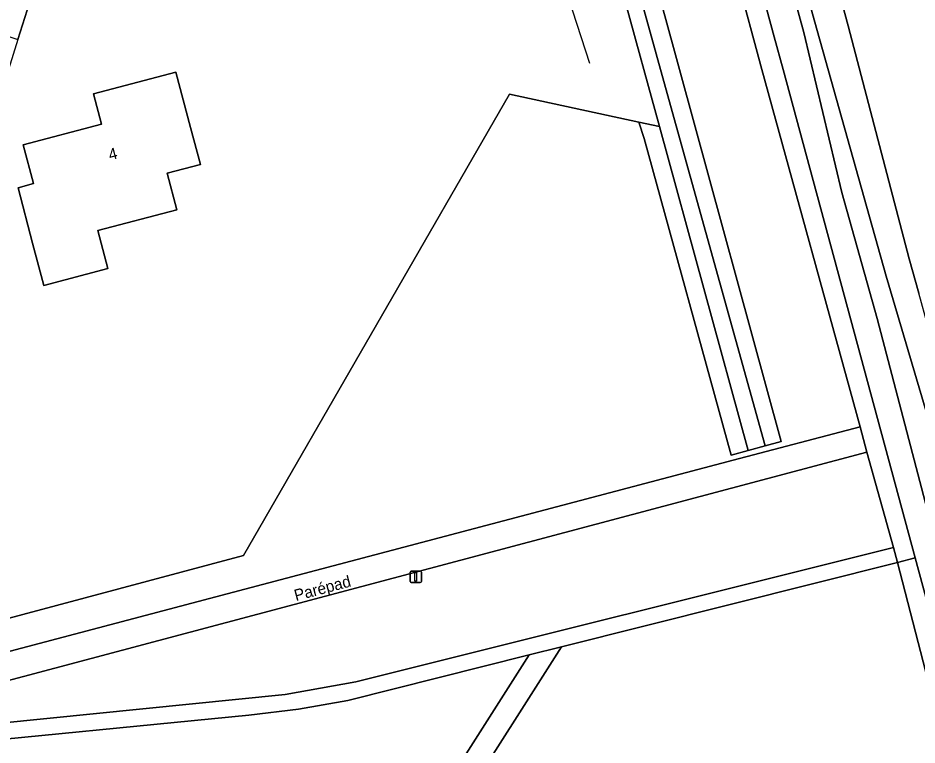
# Model space of a CAD drawing. Extents: x 162156 to 163172, y 378995 to 380779.
# Drawn here: x 162728.8 to 162807.3, y 380191 to 380254.5 of the extents above; entities that cross this region are included whole.
import ezdxf

# ---------------------------------------------------------------- set-up
doc = ezdxf.new("R2010")
doc.units = 0
for name, color, linetype in [('IMGEO_Erf', 7, 'Continuous'), ('IMGEO_Fietspad_gesloten', 7, 'Continuous'), ('IMGEO_Gemengd_bos', 7, 'Continuous'), ('IMGEO_Groenvoorziening', 7, 'Continuous'), ('IMGEO_Hek', 7, 'Continuous'), ('IMGEO_Lichtmast', 7, 'Continuous'), ('IMGEO_Naaldbos', 7, 'Continuous'), ('IMGEO_Openbare_ruimte_label', 7, 'Continuous'), ('IMGEO_Pand', 7, 'Continuous'), ('IMGEO_Pand_nummerreeks', 7, 'Continuous'), ('IMGEO_Rijbaan_lokaal_gesloten', 7, 'Continuous'), ('IMGEO_Rijbaan_lokaal_onverhard', 7, 'Continuous'), ('IMGEO_Voetpad_halfverhard', 7, 'Continuous'), ('IMGEO_Voetpad_open', 7, 'Continuous')]:
    doc.layers.add(name, color=color, linetype=linetype)

msp = doc.modelspace()

# ---------------------------------------------------------------- linework, layer by layer
at = {"layer": 'IMGEO_Erf'}
msp.add_lwpolyline([(162729.987, 380256.471), (162728.785, 380252.601), (162727.974, 380249.988), (162726.374, 380245.66), (162723.48, 380239.34), (162721.842, 380236.275), (162720.429, 380233.968), (162720.027, 380233.312), (162716.656, 380228.741), (162716.33, 380228.299), (162716.04, 380227.906), (162711.278, 380222.808), (162706.233, 380218.452), (162718.287, 380199.505), (162748.489, 380207.589), (162771.731, 380247.855), (162782.999, 380245.41), (162784.806, 380245.018), (162783.44, 380250), (162783.125, 380251.148), (162766.255, 380312.701)], dxfattribs=at)
msp.add_lwpolyline([(162743.866, 380244.932), (162744.719, 380241.706), (162741.817, 380240.939), (162742.658, 380237.76), (162735.759, 380235.935), (162736.634, 380232.624), (162731.048, 380231.146), (162730.07, 380234.846), (162728.792, 380239.679), (162730.144, 380240.037), (162729.246, 380243.433), (162736.069, 380245.237), (162735.376, 380247.858), (162742.588, 380249.765)], close=True, dxfattribs=at)
at = {"layer": 'IMGEO_Fietspad_gesloten'}
msp.add_lwpolyline([(162734.133, 380481.792), (162732.921, 380486.487), (162731.275, 380485.433), (162731.822, 380483.297), (162732.486, 380480.708), (162737.147, 380462.444), (162744.041, 380435.433), (162753.469, 380399.171), (162793.043, 380252.594), (162793.743, 380250), (162802.348, 380218.82), (162802.932, 380216.599), (162805.251, 380208.274), (162805.604, 380206.953), (162807.15, 380207.372), (162795.604, 380250), (162794.831, 380252.855), (162755.082, 380399.61), (162738.941, 380462.93)], close=True, dxfattribs=at)
at = {"layer": 'IMGEO_Gemengd_bos'}
for points in [[(162725.222, 380467.154), (162726.017, 380463.29), (162732.512, 380440.284), (162732.513, 380440.281), (162737.886, 380421.251), (162740.789, 380409.911), (162740.791, 380409.902), (162744.134, 380396.843), (162784.538, 380251.354), (162784.914, 380250), (162794.037, 380217.15), (162795.456, 380217.538), (162786.56, 380250), (162786.126, 380251.585), (162745.395, 380400.219)], [(162727.791, 380464.262), (162728.963, 380460.227), (162739.025, 380425.583), (162745.395, 380400.219), (162786.126, 380251.585), (162786.56, 380250), (162795.456, 380217.538), (162794.037, 380217.15), (162792.555, 380216.745), (162791.089, 380216.345), (162783.48, 380243.983), (162782.999, 380245.41), (162771.731, 380247.855), (162748.489, 380207.589), (162718.287, 380199.505), (162706.233, 380218.452), (162704.484, 380215.83), (162716.066, 380197.828)], [(162718.821, 380196.787), (162791.243, 380215.891), (162802.348, 380218.82), (162793.743, 380250), (162793.043, 380252.594), (162753.469, 380399.171)]]:
    msp.add_lwpolyline(points, dxfattribs=at)
for points in [[(162744.134, 380396.843), (162740.791, 380409.902), (162740.789, 380409.911), (162737.886, 380421.251), (162732.513, 380440.281), (162732.512, 380440.284), (162731.457, 380440.006), (162737.08, 380420.274), (162739.846, 380409.655), (162742.744, 380398.533), (162743.009, 380397.514), (162766.255, 380312.701), (162783.125, 380251.148), (162783.44, 380250), (162784.806, 380245.018), (162792.555, 380216.745), (162794.037, 380217.15), (162784.914, 380250), (162784.538, 380251.354)], [(162784.806, 380245.018), (162782.999, 380245.41), (162783.48, 380243.983), (162791.089, 380216.345), (162792.555, 380216.745)]]:
    msp.add_lwpolyline(points, close=True, dxfattribs=at)
at = {"layer": 'IMGEO_Groenvoorziening'}
for points in [[(162797.432, 380253.232), (162791.916, 380273.301), (162786.532, 380293.517), (162775.358, 380333.719), (162765.415, 380371.737), (162759.745, 380391.983), (162736.16, 380483.349), (162735.346, 380483.727), (162734.512, 380483.576)], [(162734.133, 380481.792), (162738.941, 380462.93), (162755.082, 380399.61), (162794.831, 380252.855), (162795.604, 380250), (162807.15, 380207.372), (162834.019, 380108.166), (162847.388, 380056.989), (162849.58, 380050.068), (162853.046, 380036.529), (162855.696, 380027.529), (162859.063, 380014.988), (162859.82, 380012.908), (162860.297, 380010.248), (162863.326, 380000), (162875.925, 379953.557)], [(162766.299, 380383.503), (162801.292, 380253.797), (162806.635, 380233.468), (162807.467, 380230.468)], [(162812.966, 380210.526), (162807.467, 380230.468), (162806.635, 380233.468), (162801.292, 380253.797), (162766.299, 380383.503)], [(162771.243, 380358.925), (162778.519, 380332.031), (162782.456, 380315.752), (162787.624, 380297.403), (162792.424, 380276.743), (162796.525, 380260.819), (162798.599, 380253.404), (162804.6, 380231.946), (162813.274, 380202.726), (162817.832, 380185.507), (162820.474, 380174.332), (162830.289, 380136.987), (162838.721, 380106.165), (162845.723, 380082.59), (162848.029, 380072.7), (162850.821, 380063.544), (162873.068, 379986.284), (162876.406, 379973.928), (162879.54, 379963.774)], [(162877.807, 379945.478), (162877.926, 379942.988), (162877.836, 379940.496), (162876.059, 379929.997), (162869.525, 379903.661), (162857.788, 379858.933), (162852.224, 379836.568), (162855.953, 379839.98), (162859.941, 379851.001), (162864.319, 379866.718), (162869.74, 379887.62), (162878.52, 379925.926), (162880.462, 379936.118), (162880.894, 379940.356), (162878.531, 379959.461), (162877.403, 379963.088), (162875.477, 379970.319), (162872.222, 379980.619), (162850.444, 380055.192), (162836.518, 380107.168), (162815.649, 380183.144), (162803.814, 380228.274), (162800.754, 380239.27), (162797.432, 380253.232)]]:
    msp.add_lwpolyline(points, dxfattribs=at)
at = {"layer": 'IMGEO_Hek'}
msp.add_lwpolyline([(162778.738, 380250.508), (162768.177, 380283.038), (162722.067, 380458.358), (162720.737, 380463.414)], dxfattribs=at)
at = {"layer": 'IMGEO_Lichtmast'}
for p, q in [((162763.028, 380205.309), (162763.028, 380206.109)), ((162763.028, 380206.109), (162763.028, 380205.309)), ((162763.128, 380206.209), (162763.918, 380206.209)), ((162763.918, 380206.209), (162763.128, 380206.209)), ((162764.018, 380206.109), (162764.018, 380205.309)), ((162764.018, 380205.309), (162764.018, 380206.109)), ((162763.918, 380205.209), (162763.128, 380205.209)), ((162763.128, 380205.209), (162763.918, 380205.209))]:
    msp.add_line(p, q, dxfattribs=at)
msp.add_lwpolyline([(162763.448, 380206.084), (162763.598, 380206.084), (162763.598, 380205.334), (162763.448, 380205.334), (162763.448, 380206.084)], dxfattribs=at)
for centre, start, end in [((162763.128, 380206.109), 90, 180), ((162763.128, 380206.109), 90, 180), ((162763.918, 380206.109), 0, 90), ((162763.918, 380206.109), 360, 90), ((162763.128, 380205.309), 180, 270), ((162763.128, 380205.309), 180, 270), ((162763.918, 380205.309), 270, 0), ((162763.918, 380205.309), 270, 0)]:
    msp.add_arc(centre, 0.1, start, end, dxfattribs=at)
at = {"layer": 'IMGEO_Naaldbos'}
for points in [[(162718.858, 380192.089), (162752.138, 380195.441), (162758.283, 380196.548), (162805.251, 380208.274), (162802.932, 380216.599), (162717.424, 380193.879)], [(162838.54, 380083.951), (162836.289, 380091.771), (162832.661, 380106.401), (162811.234, 380185.217), (162805.604, 380206.953), (162776.255, 380199.6), (162758.215, 380171.258), (162779.588, 380093.439), (162780.643, 380093.581), (162806.22, 380000)]]:
    msp.add_lwpolyline(points, dxfattribs=at)
msp.add_lwpolyline([(162721.056, 380190.903), (162731.803, 380187.774), (162737.024, 380185.747), (162742.813, 380182.703), (162750.127, 380178.223), (162753.063, 380176.112), (162756.789, 380172.742), (162773.434, 380198.894), (162757.585, 380194.923), (162753.291, 380194.171), (162748.964, 380193.637)], close=True, dxfattribs=at)
at = {"layer": 'IMGEO_Pand'}
msp.add_lwpolyline([(162743.866, 380244.932), (162742.588, 380249.765), (162735.376, 380247.858), (162736.069, 380245.237), (162729.246, 380243.433), (162730.144, 380240.037), (162728.792, 380239.679), (162730.07, 380234.846), (162731.048, 380231.146), (162736.634, 380232.624), (162735.759, 380235.935), (162742.658, 380237.76), (162741.817, 380240.939), (162744.719, 380241.706)], close=True, dxfattribs=at)
at = {"layer": 'IMGEO_Rijbaan_lokaal_gesloten'}
msp.add_lwpolyline([(162847.388, 380056.989), (162834.019, 380108.166), (162807.15, 380207.372), (162805.604, 380206.953), (162811.234, 380185.217), (162832.661, 380106.401), (162836.289, 380091.771), (162838.54, 380083.951)], dxfattribs=at)
at = {"layer": 'IMGEO_Rijbaan_lokaal_onverhard'}
for points in [[(162887.734, 379923.859), (162885.297, 379937.582), (162879.54, 379963.774), (162876.406, 379973.928), (162873.068, 379986.284), (162850.821, 380063.544), (162848.029, 380072.7), (162845.723, 380082.59), (162838.721, 380106.165), (162830.289, 380136.987), (162820.474, 380174.332), (162817.832, 380185.507), (162813.274, 380202.726), (162804.6, 380231.946), (162798.599, 380253.404), (162796.525, 380260.819), (162792.424, 380276.743), (162787.624, 380297.403), (162782.456, 380315.752), (162778.519, 380332.031), (162771.243, 380358.925), (162764.081, 380387.552), (162762.982, 380391.944), (162737.511, 380495.432)], [(162765.415, 380371.737), (162775.358, 380333.719), (162786.532, 380293.517), (162791.916, 380273.301), (162797.432, 380253.232), (162800.754, 380239.27), (162803.814, 380228.274), (162815.649, 380183.144), (162836.518, 380107.168), (162850.444, 380055.192), (162872.222, 379980.619), (162875.477, 379970.319), (162877.403, 379963.088)]]:
    msp.add_lwpolyline(points, dxfattribs=at)
at = {"layer": 'IMGEO_Voetpad_halfverhard'}
msp.add_lwpolyline([(162719.036, 380190.705), (162721.056, 380190.903), (162748.964, 380193.637), (162753.291, 380194.171), (162757.585, 380194.923), (162773.434, 380198.894), (162776.255, 380199.6), (162805.604, 380206.953), (162805.251, 380208.274), (162758.283, 380196.548), (162752.138, 380195.441), (162718.858, 380192.089)], dxfattribs=at)
msp.add_lwpolyline([(162776.255, 380199.6), (162773.434, 380198.894), (162756.789, 380172.742), (162758.215, 380171.258)], close=True, dxfattribs=at)
at = {"layer": 'IMGEO_Voetpad_open'}
msp.add_lwpolyline([(162726.015, 380253.554), (162728.785, 380252.601), (162729.987, 380256.471), (162727.064, 380257.059), (162724.29, 380257.618), (162723.325, 380253.61)], close=True, dxfattribs=at)
for points in [[(162802.932, 380216.599), (162802.348, 380218.82), (162791.243, 380215.891), (162718.821, 380196.787)], [(162717.424, 380193.879), (162802.932, 380216.599)]]:
    msp.add_lwpolyline(points, dxfattribs=at)

# ---------------------------------------------------------------- texts
at = {"layer": 'IMGEO_Openbare_ruimte_label'}
msp.add_text('Parépad', height=1, rotation=14.89819, dxfattribs=at).set_placement((162753.061, 380203.59))
at = {"layer": 'IMGEO_Pand_nummerreeks'}
msp.add_text('4', height=1, rotation=14.81009, dxfattribs=at).set_placement((162736.836, 380242.048))

doc.saveas('drawing.dxf')
